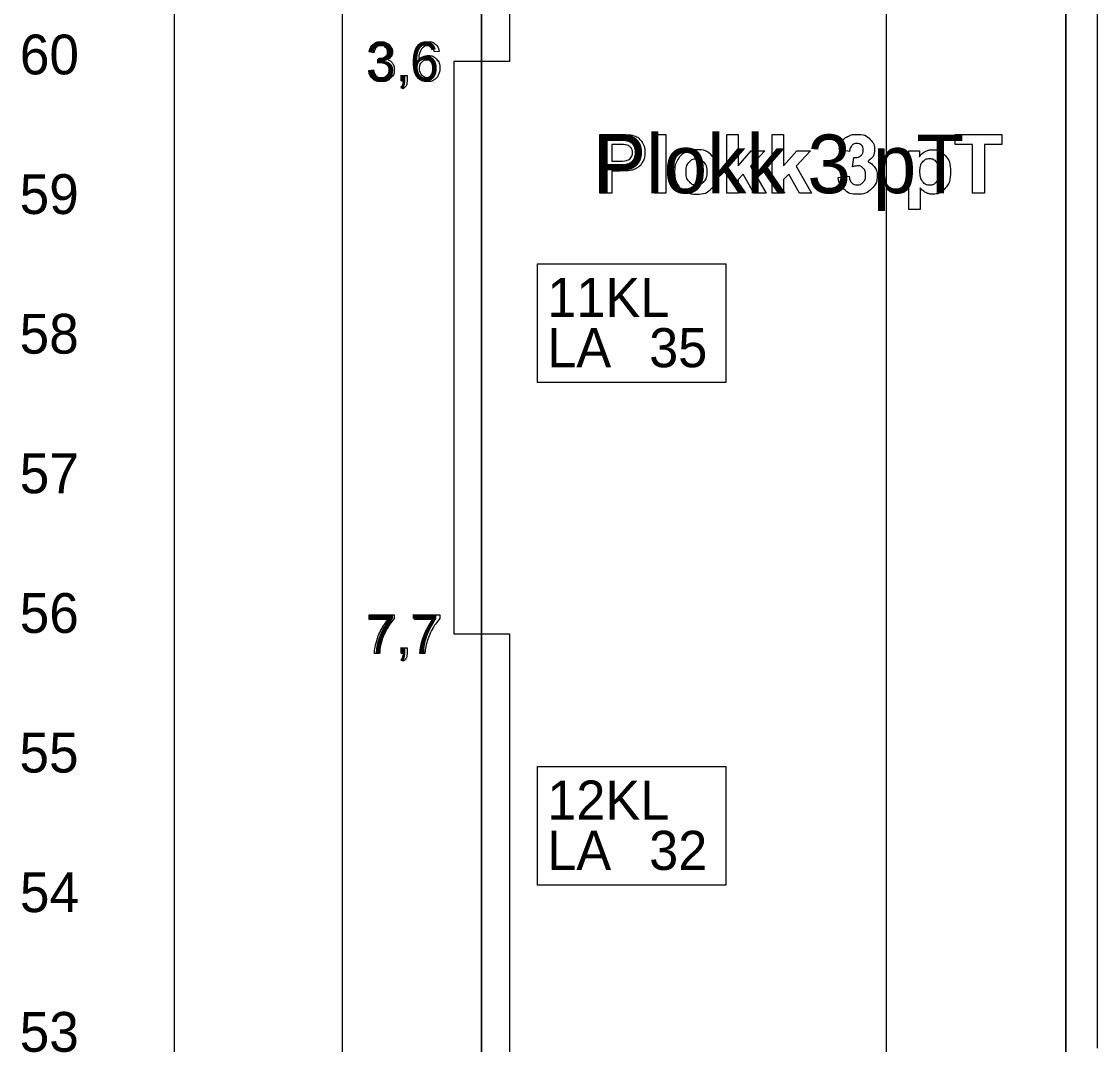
# Model space of a CAD drawing. Extents: x 532503 to 539665, y 6557663 to 6561526.
# Drawn here: x 537986.9 to 538141.1, y 6559684.2 to 6559830.7 of the extents above; entities that cross this region are included whole.
import ezdxf

# ---------------------------------------------------------------- set-up
doc = ezdxf.new("R2010")
doc.units = 0
for name, color, linetype in [('GEOLPUNKT', 7, 'Continuous'), ('Kaitsevöönd', 7, 'Continuous'), ('mõõtpost vasak', 7, 'Continuous'), ('Plokid', 7, 'Continuous'), ('Proovid', 7, 'Continuous'), ('Täide', 7, 'Continuous')]:
    doc.layers.add(name, color=color, linetype=linetype)

msp = doc.modelspace()

# ---------------------------------------------------------------- linework, layer by layer
at = {"layer": 'GEOLPUNKT'}
msp.add_line((538052.87, 6559897), (538052.87, 6559597), dxfattribs=at)
at = {"layer": 'Kaitsevöönd'}
for p, q in [((538136.56, 6559942.41), (538136.56, 6559632.51)), ((538136.56, 6559632.51), (538136.56, 6559942.41)), ((538110.85, 6559941), (538110.85, 6559619.77)), ((538110.85, 6559940.99), (538110.85, 6559619.77))]:
    msp.add_line(p, q, dxfattribs=at)
at = {"layer": 'mõõtpost vasak'}
msp.add_line((538008.86, 6559586), (538008.86, 6560006), dxfattribs=at)
at = {"layer": 'Plokid'}
for p, q in [((538141.11, 6559683.67), (538141.11, 6559935.03)), ((538052.87, 6559647), (538052.87, 6559889))]:
    msp.add_line(p, q, dxfattribs=at)
for points in [[(538069.81, 6559806.13), (538069.81, 6559814.53), (538072.53, 6559814.53)], [(538077.62, 6559806.13), (538077.62, 6559814.53), (538079.24, 6559814.53), (538079.24, 6559806.13), (538077.62, 6559806.13)], [(538087.99, 6559806.13), (538087.99, 6559814.53), (538089.61, 6559814.53), (538089.61, 6559810.07), (538091.49, 6559812.22), (538093.47, 6559812.22), (538091.39, 6559809.99), (538093.62, 6559806.13), (538091.88, 6559806.13), (538090.35, 6559808.87), (538089.61, 6559808.08), (538089.61, 6559806.13), (538087.99, 6559806.13)], [(538094.52, 6559806.13), (538094.52, 6559814.53), (538096.13, 6559814.53), (538096.13, 6559810.07), (538098.01, 6559812.22), (538100, 6559812.22), (538097.92, 6559809.99), (538100.14, 6559806.13), (538098.41, 6559806.13), (538096.88, 6559808.87), (538096.13, 6559808.08), (538096.13, 6559806.13), (538094.52, 6559806.13)], [(538123.21, 6559806.13), (538123.21, 6559813.11), (538120.72, 6559813.11), (538120.72, 6559814.53), (538127.4, 6559814.53), (538127.4, 6559813.11), (538124.91, 6559813.11), (538124.91, 6559806.13), (538123.21, 6559806.13)], [(538071.5, 6559813.11), (538071.5, 6559810.72), (538072.43, 6559810.72)], [(538072.32, 6559813.11), (538071.5, 6559813.11)], [(538105.56, 6559812.12), (538104.08, 6559812.37)], [(538106.03, 6559809.92), (538106.21, 6559811.23)], [(538114.09, 6559812.22), (538115.6, 6559812.22), (538115.6, 6559811.32)], [(538115.7, 6559806.88), (538115.7, 6559803.81), (538114.09, 6559803.81), (538114.09, 6559812.22)], [(538072.61, 6559809.3), (538071.5, 6559809.3), (538071.5, 6559806.13), (538069.81, 6559806.13)], [(538103.96, 6559808.37), (538105.51, 6559808.56)]]:
    msp.add_lwpolyline(points, dxfattribs=at)
for points in [[(538072.53, 6559814.53), (538074.07, 6559814.53), (538074.54, 6559814.4), (538075.27, 6559814.21), (538075.75, 6559813.58), (538076.24, 6559812.95), (538076.24, 6559811.95), (538076.24, 6559811.17), (538075.96, 6559810.65), (538075.68, 6559810.12), (538075.25, 6559809.82), (538074.81, 6559809.52), (538074.37, 6559809.42), (538073.76, 6559809.3), (538072.61, 6559809.3)], [(538104.08, 6559812.37), (538104.23, 6559813.13), (538104.54, 6559813.58), (538104.86, 6559814.04), (538105.42, 6559814.3), (538105.97, 6559814.56), (538106.67, 6559814.56), (538107.85, 6559814.56), (538108.57, 6559813.81), (538109.16, 6559813.19), (538109.16, 6559812.41), (538109.16, 6559811.31), (538107.95, 6559810.65), (538108.67, 6559810.49), (538109.1, 6559809.95), (538109.53, 6559809.42), (538109.53, 6559808.65), (538109.53, 6559807.55), (538108.73, 6559806.77), (538107.92, 6559805.99), (538106.72, 6559805.99), (538105.58, 6559805.99), (538104.83, 6559806.65), (538104.08, 6559807.3), (538103.96, 6559808.37)], [(538072.43, 6559810.72), (538073.43, 6559810.72), (538073.77, 6559810.85), (538074.11, 6559810.98), (538074.3, 6559811.27), (538074.49, 6559811.55), (538074.49, 6559811.92), (538074.49, 6559812.38), (538074.22, 6559812.68), (538073.95, 6559812.98), (538073.54, 6559813.05), (538073.24, 6559813.11), (538072.32, 6559813.11)], [(538106.21, 6559811.23), (538106.86, 6559811.22), (538107.2, 6559811.51), (538107.55, 6559811.81), (538107.55, 6559812.31), (538107.55, 6559812.73), (538107.3, 6559812.99), (538107.04, 6559813.24), (538106.62, 6559813.24), (538106.21, 6559813.24), (538105.92, 6559812.95), (538105.63, 6559812.66), (538105.56, 6559812.12)], [(538080.5, 6559809.26), (538080.5, 6559810.06), (538080.9, 6559810.81), (538081.3, 6559811.56), (538082.02, 6559811.96), (538082.75, 6559812.35), (538083.64, 6559812.35), (538085.02, 6559812.35), (538085.91, 6559811.46), (538086.79, 6559810.56), (538086.79, 6559809.19), (538086.79, 6559807.81), (538085.9, 6559806.9), (538085.01, 6559806), (538083.65, 6559806), (538082.82, 6559806), (538082.06, 6559806.37), (538081.3, 6559806.75), (538080.9, 6559807.48), (538080.5, 6559808.21), (538080.5, 6559809.26)], [(538082.16, 6559809.17), (538082.16, 6559808.27), (538082.59, 6559807.79), (538083.02, 6559807.31), (538083.65, 6559807.31), (538084.28, 6559807.31), (538084.71, 6559807.79), (538085.13, 6559808.27), (538085.13, 6559809.19), (538085.13, 6559810.08), (538084.71, 6559810.56), (538084.28, 6559811.04), (538083.65, 6559811.04), (538083.02, 6559811.04), (538082.59, 6559810.56), (538082.16, 6559810.08), (538082.16, 6559809.17)], [(538115.6, 6559811.32), (538115.89, 6559811.78), (538116.39, 6559812.07), (538116.89, 6559812.35), (538117.49, 6559812.35), (538118.55, 6559812.35), (538119.29, 6559811.52), (538120.03, 6559810.69), (538120.03, 6559809.21), (538120.03, 6559807.68), (538119.29, 6559806.84), (538118.54, 6559806), (538117.48, 6559806), (538116.98, 6559806), (538116.57, 6559806.2), (538116.16, 6559806.4), (538115.7, 6559806.88)], [(538115.68, 6559809.28), (538115.68, 6559808.25), (538116.09, 6559807.76), (538116.5, 6559807.28), (538117.08, 6559807.28), (538117.65, 6559807.28), (538118.02, 6559807.72), (538118.39, 6559808.17), (538118.39, 6559809.2), (538118.39, 6559810.15), (538118.01, 6559810.62), (538117.62, 6559811.08), (538117.05, 6559811.08), (538116.46, 6559811.08), (538116.07, 6559810.62), (538115.68, 6559810.17), (538115.68, 6559809.28)], [(538105.51, 6559808.56), (538105.59, 6559807.96), (538105.91, 6559807.64), (538106.24, 6559807.33), (538106.7, 6559807.33), (538107.2, 6559807.33), (538107.54, 6559807.7), (538107.88, 6559808.08), (538107.88, 6559808.72), (538107.88, 6559809.33), (538107.56, 6559809.69), (538107.23, 6559810.04), (538106.76, 6559810.04), (538106.46, 6559810.04), (538106.03, 6559809.92)]]:
    msp.add_open_spline(points, degree=3, dxfattribs=at)
at = {"layer": 'Proovid'}
for points in [[(538052.87, 6559889), (538056.87, 6559889), (538056.87, 6559825), (538052.87, 6559825)], [(538052.87, 6559825), (538048.87, 6559825), (538048.87, 6559743), (538052.87, 6559743)], [(538060.87, 6559796), (538087.87, 6559796), (538087.87, 6559779), (538060.87, 6559779)], [(538052.87, 6559743), (538056.87, 6559743), (538056.87, 6559681), (538052.87, 6559681)], [(538060.87, 6559724), (538087.87, 6559724), (538087.87, 6559707), (538060.87, 6559707)]]:
    msp.add_lwpolyline(points, close=True, dxfattribs=at)
for points in [[(538037.44, 6559826.25), (538036.75, 6559826.38)], [(538046.77, 6559826.43), (538046.09, 6559826.38)], [(538038.04, 6559824.86), (538038.12, 6559825.46)], [(538036.68, 6559823.69), (538037.37, 6559823.78)], [(538041.4, 6559822.2), (538041.4, 6559822.99), (538042.18, 6559822.99), (538042.18, 6559822.2)], [(538041.79, 6559822.2), (538041.4, 6559822.2)], [(538041.55, 6559821.1), (538041.35, 6559821.39)], [(538036.73, 6559745.07), (538036.73, 6559745.73), (538040.35, 6559745.73), (538040.35, 6559745.2)], [(538039.47, 6559745.07), (538036.73, 6559745.07)], [(538043.25, 6559745.07), (538043.25, 6559745.73), (538046.87, 6559745.73), (538046.87, 6559745.2)], [(538045.99, 6559745.07), (538043.25, 6559745.07)], [(538038.22, 6559740.2), (538037.51, 6559740.2)], [(538041.4, 6559740.2), (538041.4, 6559740.99), (538042.18, 6559740.99), (538042.18, 6559740.2)], [(538041.79, 6559740.2), (538041.4, 6559740.2)], [(538044.74, 6559740.2), (538044.03, 6559740.2)], [(538041.55, 6559739.1), (538041.35, 6559739.39)]]:
    msp.add_lwpolyline(points, dxfattribs=at)
for points in [[(538036.75, 6559826.38), (538036.88, 6559827.07), (538037.33, 6559827.45), (538037.77, 6559827.83), (538038.44, 6559827.83), (538038.9, 6559827.83), (538039.28, 6559827.63), (538039.67, 6559827.43), (538039.87, 6559827.09), (538040.08, 6559826.75), (538040.08, 6559826.37), (538040.08, 6559826.01), (538039.88, 6559825.71), (538039.69, 6559825.42), (538039.31, 6559825.24), (538039.8, 6559825.13), (538040.08, 6559824.77), (538040.35, 6559824.4), (538040.35, 6559823.86), (538040.35, 6559823.13), (538039.82, 6559822.62), (538039.28, 6559822.11), (538038.46, 6559822.11), (538037.73, 6559822.11), (538037.24, 6559822.55), (538036.75, 6559822.99), (538036.68, 6559823.69)], [(538046.09, 6559826.38), (538046, 6559826.78), (538045.83, 6559826.97), (538045.55, 6559827.26), (538045.14, 6559827.26), (538044.81, 6559827.26), (538044.56, 6559827.08), (538044.24, 6559826.84), (538044.05, 6559826.39), (538043.86, 6559825.93), (538043.85, 6559825.09), (538044.1, 6559825.47), (538044.46, 6559825.65), (538044.82, 6559825.84), (538045.22, 6559825.84), (538045.9, 6559825.84), (538046.39, 6559825.33), (538046.87, 6559824.83), (538046.87, 6559824.02), (538046.87, 6559823.5), (538046.64, 6559823.04), (538046.42, 6559822.59), (538046.02, 6559822.35), (538045.62, 6559822.11), (538045.12, 6559822.11), (538044.26, 6559822.11), (538043.71, 6559822.74), (538043.17, 6559823.37), (538043.17, 6559824.83), (538043.17, 6559826.45), (538043.77, 6559827.18), (538044.3, 6559827.83), (538045.18, 6559827.83), (538045.84, 6559827.83), (538046.27, 6559827.46), (538046.69, 6559827.08), (538046.77, 6559826.43)], [(538038.12, 6559825.46), (538038.18, 6559825.45), (538038.23, 6559825.45), (538038.67, 6559825.45), (538039.02, 6559825.68), (538039.37, 6559825.91), (538039.37, 6559826.39), (538039.37, 6559826.77), (538039.11, 6559827.01), (538038.86, 6559827.26), (538038.45, 6559827.26), (538038.05, 6559827.26), (538037.78, 6559827.01), (538037.52, 6559826.76), (538037.44, 6559826.25)], [(538037.37, 6559823.78), (538037.49, 6559823.19), (538037.77, 6559822.94), (538038.06, 6559822.68), (538038.47, 6559822.68), (538038.95, 6559822.68), (538039.29, 6559823.01), (538039.62, 6559823.35), (538039.62, 6559823.85), (538039.62, 6559824.32), (538039.31, 6559824.63), (538039, 6559824.94), (538038.52, 6559824.94), (538038.33, 6559824.94), (538038.04, 6559824.86)], [(538043.96, 6559824.02), (538043.96, 6559823.66), (538044.11, 6559823.34), (538044.26, 6559823.01), (538044.53, 6559822.84), (538044.8, 6559822.67), (538045.1, 6559822.67), (538045.54, 6559822.67), (538045.85, 6559823.03), (538046.16, 6559823.38), (538046.16, 6559823.98), (538046.16, 6559824.56), (538045.86, 6559824.9), (538045.55, 6559825.23), (538045.08, 6559825.23), (538044.61, 6559825.23), (538044.29, 6559824.9), (538043.96, 6559824.56), (538043.96, 6559824.02)], [(538041.35, 6559821.39), (538041.57, 6559821.49), (538041.67, 6559821.67), (538041.78, 6559821.86), (538041.79, 6559822.2)], [(538042.18, 6559822.2), (538042.18, 6559821.77), (538042.03, 6559821.51), (538041.88, 6559821.24), (538041.55, 6559821.1)], [(538037.51, 6559740.2), (538037.52, 6559740.87), (538037.77, 6559741.8), (538038.02, 6559742.74), (538038.48, 6559743.61), (538038.94, 6559744.48), (538039.47, 6559745.07)], [(538040.35, 6559745.2), (538039.82, 6559744.63), (538039.29, 6559743.68), (538038.77, 6559742.74), (538038.48, 6559741.74), (538038.27, 6559741.04), (538038.22, 6559740.2)], [(538044.03, 6559740.2), (538044.04, 6559740.87), (538044.29, 6559741.8), (538044.54, 6559742.74), (538045, 6559743.61), (538045.47, 6559744.48), (538045.99, 6559745.07)], [(538046.87, 6559745.2), (538046.34, 6559744.63), (538045.81, 6559743.68), (538045.29, 6559742.74), (538045, 6559741.74), (538044.8, 6559741.04), (538044.74, 6559740.2)], [(538041.35, 6559739.39), (538041.57, 6559739.49), (538041.67, 6559739.67), (538041.78, 6559739.86), (538041.79, 6559740.2)], [(538042.18, 6559740.2), (538042.18, 6559739.77), (538042.03, 6559739.51), (538041.88, 6559739.24), (538041.55, 6559739.1)]]:
    msp.add_open_spline(points, degree=3, dxfattribs=at)
at = {"layer": 'Täide'}
msp.add_line((538032.86, 6559875.31), (538032.86, 6559636), dxfattribs=at)
for points in [[(538032.86, 6559895.85), (538032.86, 6559636), (538032.86, 6559597)], [(538032.86, 6559887.61), (538032.86, 6559636), (538032.86, 6559597)], [(538032.86, 6559875.31), (538032.86, 6559636), (538032.86, 6559597)]]:
    msp.add_lwpolyline(points, dxfattribs=at)

# ---------------------------------------------------------------- texts
at = {"layer": 'mõõtpost vasak'}
for s, p in [('60', (537986.69, 6559823.15)), ('59', (537986.66, 6559803.15)), ('58', (537986.66, 6559783.15)), ('57', (537986.67, 6559763.15)), ('56', (537986.67, 6559743.15)), ('55', (537986.63, 6559723.15)), ('54', (537986.7, 6559703.15)), ('53', (537986.67, 6559683.15))]:
    msp.add_text(s, height=5.7, dxfattribs=at).set_placement(p)
at = {"layer": 'Plokid'}
msp.add_text('Plokk 3 pT', height=8.4, rotation=360, dxfattribs=at).set_placement((538068.95, 6559806.13))
at = {"layer": 'Proovid'}
for s, p in [('3,6', (538036.36, 6559822.2)), ('11KL', (538062.27, 6559788.4)), ('LA', (538062.27, 6559781.2)), ('35', (538076.87, 6559781.2)), ('7,7', (538036.36, 6559740.2)), ('12KL', (538062.27, 6559716.4)), ('LA', (538062.27, 6559709.2)), ('32', (538076.87, 6559709.2))]:
    msp.add_text(s, height=5.6, dxfattribs=at).set_placement(p)

doc.saveas('drawing.dxf')
